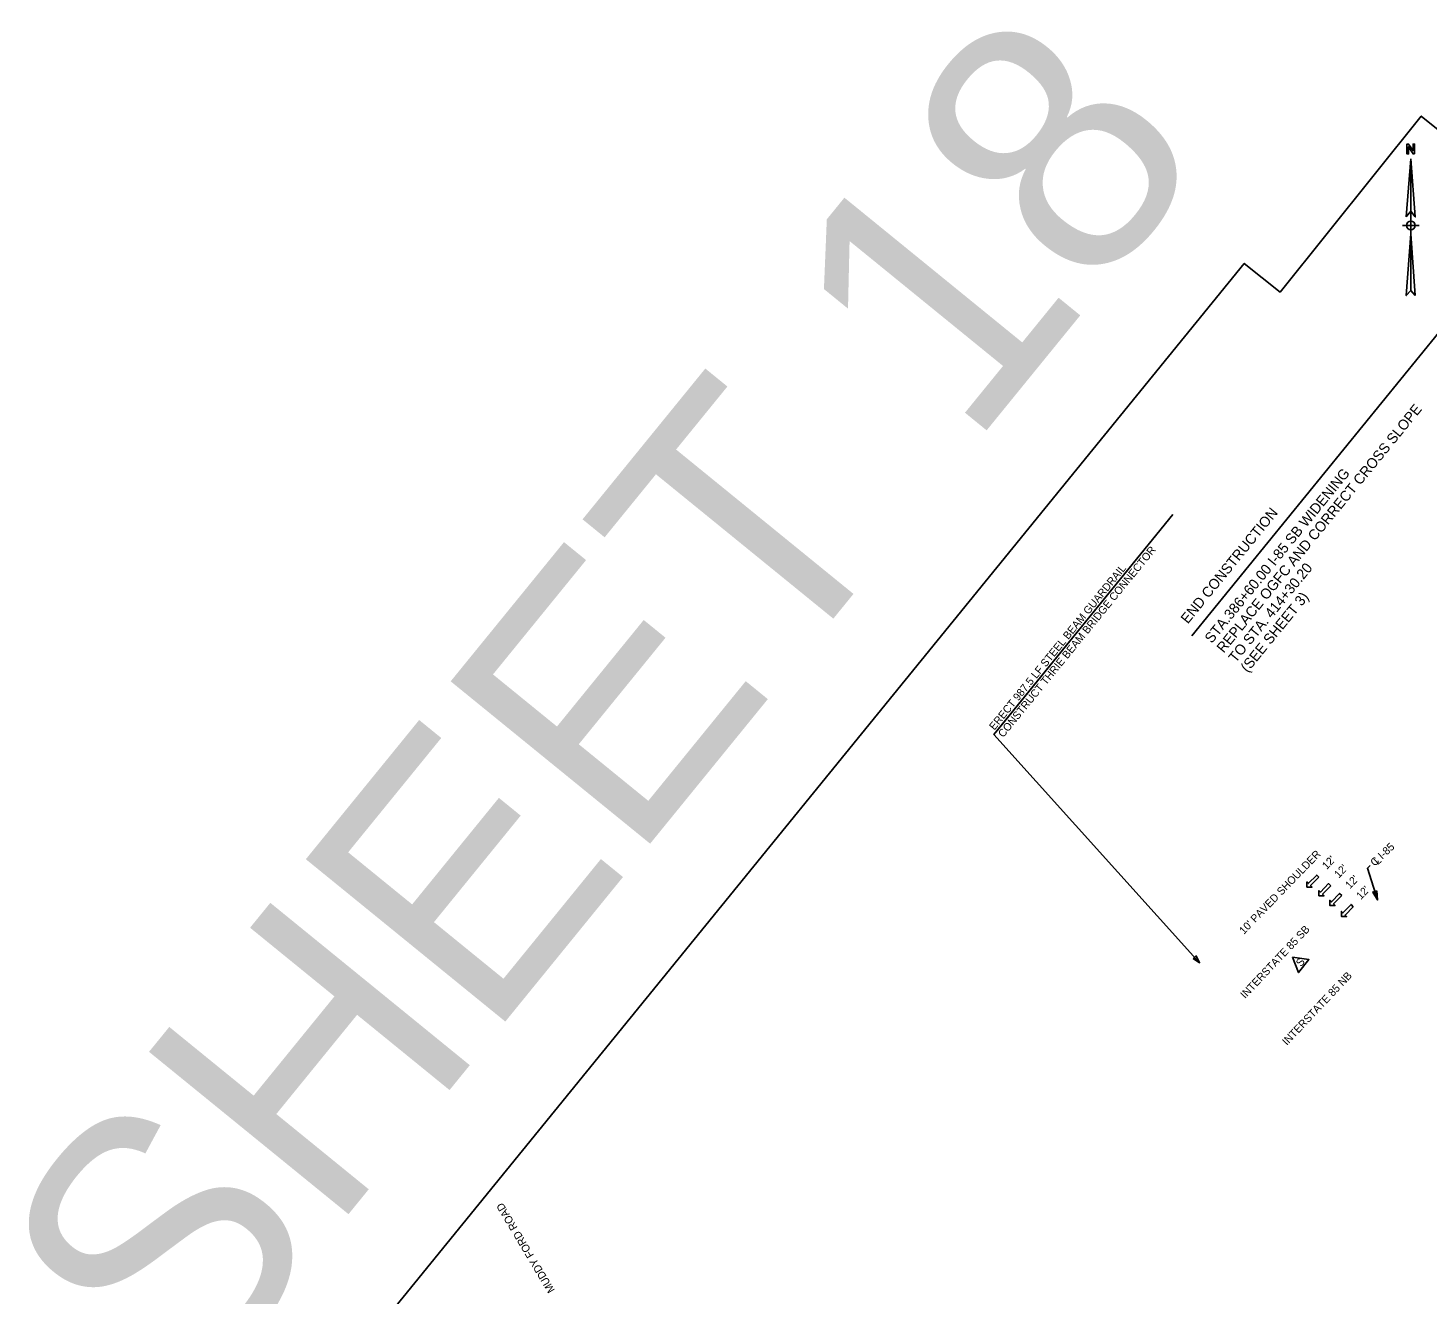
# Model space of a CAD drawing. Extents: x 1615766 to 1617965, y 1099429 to 1101416.
# Drawn here: x 1615766 to 1616854, y 1100369 to 1101353 of the extents above; entities that cross this region are included whole.
import ezdxf

# ---------------------------------------------------------------- set-up
doc = ezdxf.new("R2010")
doc.units = 0
for name, color, linetype in [('RD_EX_Bldg', 7, 'Continuous'), ('RD_EX_Driveway', 7, 'Continuous'), ('RD_EX_Fence_ChLk', 7, 'Continuous'), ('RD_EX_H2O_WetLd', 7, 'Continuous'), ('RD_EX_Misc_Golf_Teebox', 7, 'Continuous'), ('RD_EX_Road', 7, 'Continuous'), ('RD_EX_UT', 7, 'Continuous')]:
    doc.layers.add(name, color=color, linetype=linetype)

msp = doc.modelspace()

# ---------------------------------------------------------------- linework, layer by layer
at = {"layer": 'RD_EX_Bldg'}
for points in [[(1616769.3, 1100692.8), (1616767.6, 1100694.5), (1616761.1, 1100687.9), (1616760, 1100689.1), (1616760, 1100685.1), (1616764, 1100685.1), (1616762.9, 1100686.3)], [(1616778.7, 1100686.1), (1616776.9, 1100687.8), (1616770.5, 1100681.3), (1616769.4, 1100682.4), (1616769.4, 1100678.4), (1616773.4, 1100678.4), (1616772.2, 1100679.6)], [(1616787.1, 1100678.5), (1616785.4, 1100680.2), (1616779, 1100673.6), (1616777.8, 1100674.8), (1616777.9, 1100670.8), (1616781.9, 1100670.8), (1616780.7, 1100672)], [(1616796.1, 1100669.9), (1616794.4, 1100671.6), (1616788, 1100665), (1616786.8, 1100666.2), (1616786.9, 1100662.2), (1616790.9, 1100662.2), (1616789.7, 1100663.3)]]:
    msp.add_lwpolyline(points, close=True, dxfattribs=at)
at = {"layer": 'RD_EX_Driveway'}
msp.add_line((1616655.8, 1100974.8), (1616518.1, 1100805.7), dxfattribs=at)
msp.add_lwpolyline([(1616655.8, 1100974.8), (1616516.6, 1100803.8), (1616676.5, 1100626.3)], dxfattribs=at)
msp.add_lwpolyline([(1616671.5, 1100629.6), (1616676.5, 1100626.3), (1616673.8, 1100631.7)], close=True, dxfattribs=at)
at = {"layer": 'RD_EX_Fence_ChLk'}
msp.add_lwpolyline([(1616368.7, 1099765.8), (1616621.6, 1099560), (1617489.2, 1100625.8), (1617256.2, 1100856.1), (1617080.1, 1101099), (1616848.9, 1101284.7), (1616739.1, 1101147.9), (1616711.3, 1101170.2), (1615865, 1100129.8), (1615884.6, 1100113.8), (1615821.9, 1100036.8), (1616095.1, 1099888.9)], close=True, dxfattribs=at)
msp.add_lwpolyline([(1616368.7, 1099765.8), (1616621.6, 1099560), (1617489.2, 1100625.8), (1617256.2, 1100856.1), (1617080.1, 1101099), (1616848.9, 1101284.7), (1616739.1, 1101147.9), (1616711.3, 1101170.2), (1615865, 1100129.8), (1615884.6, 1100113.8), (1615821.9, 1100036.8), (1616095.1, 1099888.9)], close=True, dxfattribs=at)
at = {"layer": 'RD_EX_H2O_WetLd'}
msp.add_lwpolyline([(1616815, 1100675.2), (1616807.1, 1100699.8), (1616809.3, 1100701.8)], dxfattribs=at)
msp.add_lwpolyline([(1616814.5, 1100682.3), (1616811.2, 1100681.3), (1616815, 1100675.2)], close=True, dxfattribs=at)
at = {"layer": 'RD_EX_Misc_Golf_Teebox'}
msp.add_lwpolyline([(1616670.4, 1100880.5), (1616862.6, 1101116.5), (1617041.8, 1100911.4)], dxfattribs=at)
msp.add_lwpolyline([(1616748.7, 1100630.7), (1616753.4, 1100618.6), (1616761.6, 1100628.7)], close=True, dxfattribs=at)
at = {"layer": 'RD_EX_UT'}
for p, q in [((1616840.7, 1101251.6), (1616837.3, 1101206.3)), ((1616840.7, 1101210.9), (1616837.3, 1101206.3)), ((1616840.7, 1101210.9), (1616840.7, 1101193.1)), ((1616847.3, 1101199.7), (1616834.3, 1101199.7)), ((1616840.7, 1101193.1), (1616844.2, 1101145.2)), ((1616844.2, 1101145.2), (1616840.7, 1101149.1))]:
    msp.add_line(p, q, dxfattribs=at)
msp.add_lwpolyline([(1616843.7, 1101255.4), (1616842.5, 1101255.4), (1616839, 1101260.9), (1616839, 1101260.1), (1616839, 1101255.4), (1616837.8, 1101255.4), (1616837.8, 1101263), (1616839, 1101263), (1616842.5, 1101257.9), (1616842.5, 1101258.4), (1616842.5, 1101263), (1616843.7, 1101263), (1616843.7, 1101255.4)], dxfattribs=at)
for points in [[(1616840.7, 1101251.6), (1616844.2, 1101206.3), (1616840.7, 1101210.9)], [(1616840.7, 1101193.1), (1616840.7, 1101149.1), (1616837.3, 1101145.2)]]:
    msp.add_lwpolyline(points, close=True, dxfattribs=at)
msp.add_circle((1616840.8, 1101199.7), 3.45, dxfattribs=at)

# ---------------------------------------------------------------- texts
at = {"layer": 'RD_EX_Driveway'}
for s, p in [('CONSTRUCT THRIE BEAM BRIDGE CONNECTOR', (1616523.9, 1100801)), ('ERECT 987.5 LF STEEL BEAM GUARDRAIL', (1616517, 1100806.7))]:
    msp.add_text(s, height=6, rotation=50.8545, dxfattribs=at).set_placement(p)
at = {"layer": 'RD_EX_H2O_WetLd'}
for s, rotation, p in [('C I-85', 42.8848, (1616812.7, 1100700.9)), ('L', 42.8848, (1616815.2, 1100702.1)), ('INTERSTATE 85 SB', 46.7497, (1616712, 1100598)), ('INTERSTATE 85 NB', 46.7497, (1616744.5, 1100561.6)), ('MUDDY FORD ROAD', 120.8188, (1616175.4, 1100371.7))]:
    msp.add_text(s, height=6, rotation=rotation, dxfattribs=at).set_placement(p)
at = {"layer": 'RD_EX_Misc_Golf_Teebox'}
for s, height, rotation, p in [('REPLACE OGFC AND CORRECT CROSS SLOPE ', 8, 50.8561, (1616695.3, 1100866.7)), ('STA.386+60.00 I-85 SB WIDENING', 8, 50.8561, (1616686, 1100874.2)), ('END CONSTRUCTION', 8, 50.8561, (1616667.4, 1100889.4)), ('TO STA. 414+30.20', 8, 50.8561, (1616704.6, 1100859.1)), ('(SEE SHEET 3)', 8, 50.8561, (1616713.9, 1100851.5)), ("10' PAVED SHOULDER", 6, 45.9516, (1616711, 1100648)), ("12'", 6, 45.8739, (1616775.4, 1100698.4)), ("12'", 6, 45.8739, (1616784.8, 1100691.7)), ("12'", 6, 45.8739, (1616793.4, 1100683.3)), ("12'", 6, 45.8739, (1616802, 1100675)), ('S', 6, 50.8545, (1616755.5, 1100622.8))]:
    msp.add_text(s, height=height, rotation=rotation, dxfattribs=at).set_placement(p)
at = {"layer": 'RD_EX_Road'}
msp.add_text('SHEET 18', height=200, rotation=50.8545, dxfattribs=at).set_placement((1615888.3, 1100275.4))

doc.saveas('drawing.dxf')
